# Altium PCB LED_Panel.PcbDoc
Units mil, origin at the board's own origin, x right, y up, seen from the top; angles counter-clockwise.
Board outline 1969 x 1969 mil, 2 copper layers (Top Layer, Bottom Layer); 87 components, 51 nets, 309 pads, 50 vias.
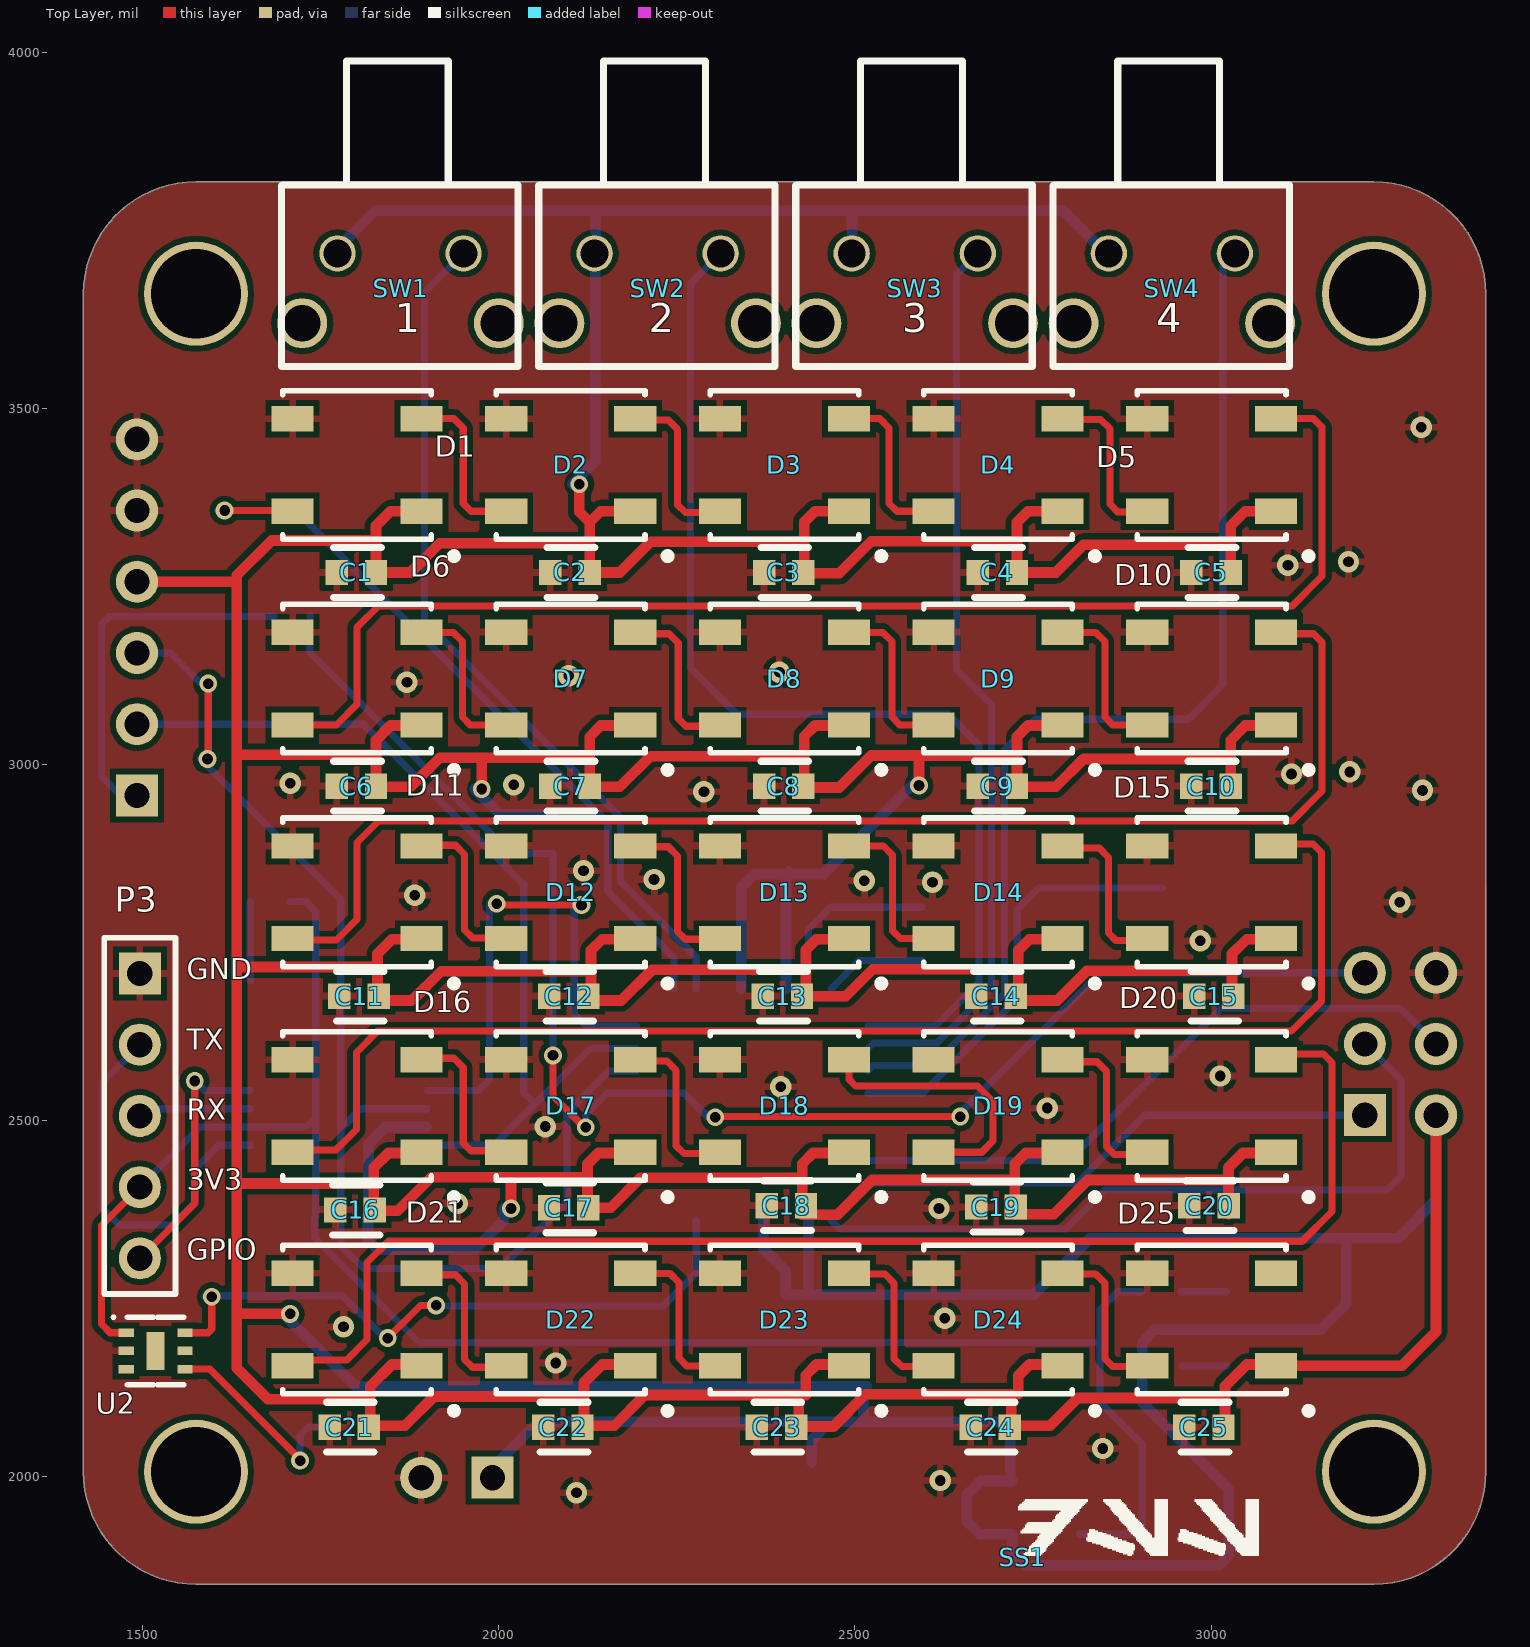
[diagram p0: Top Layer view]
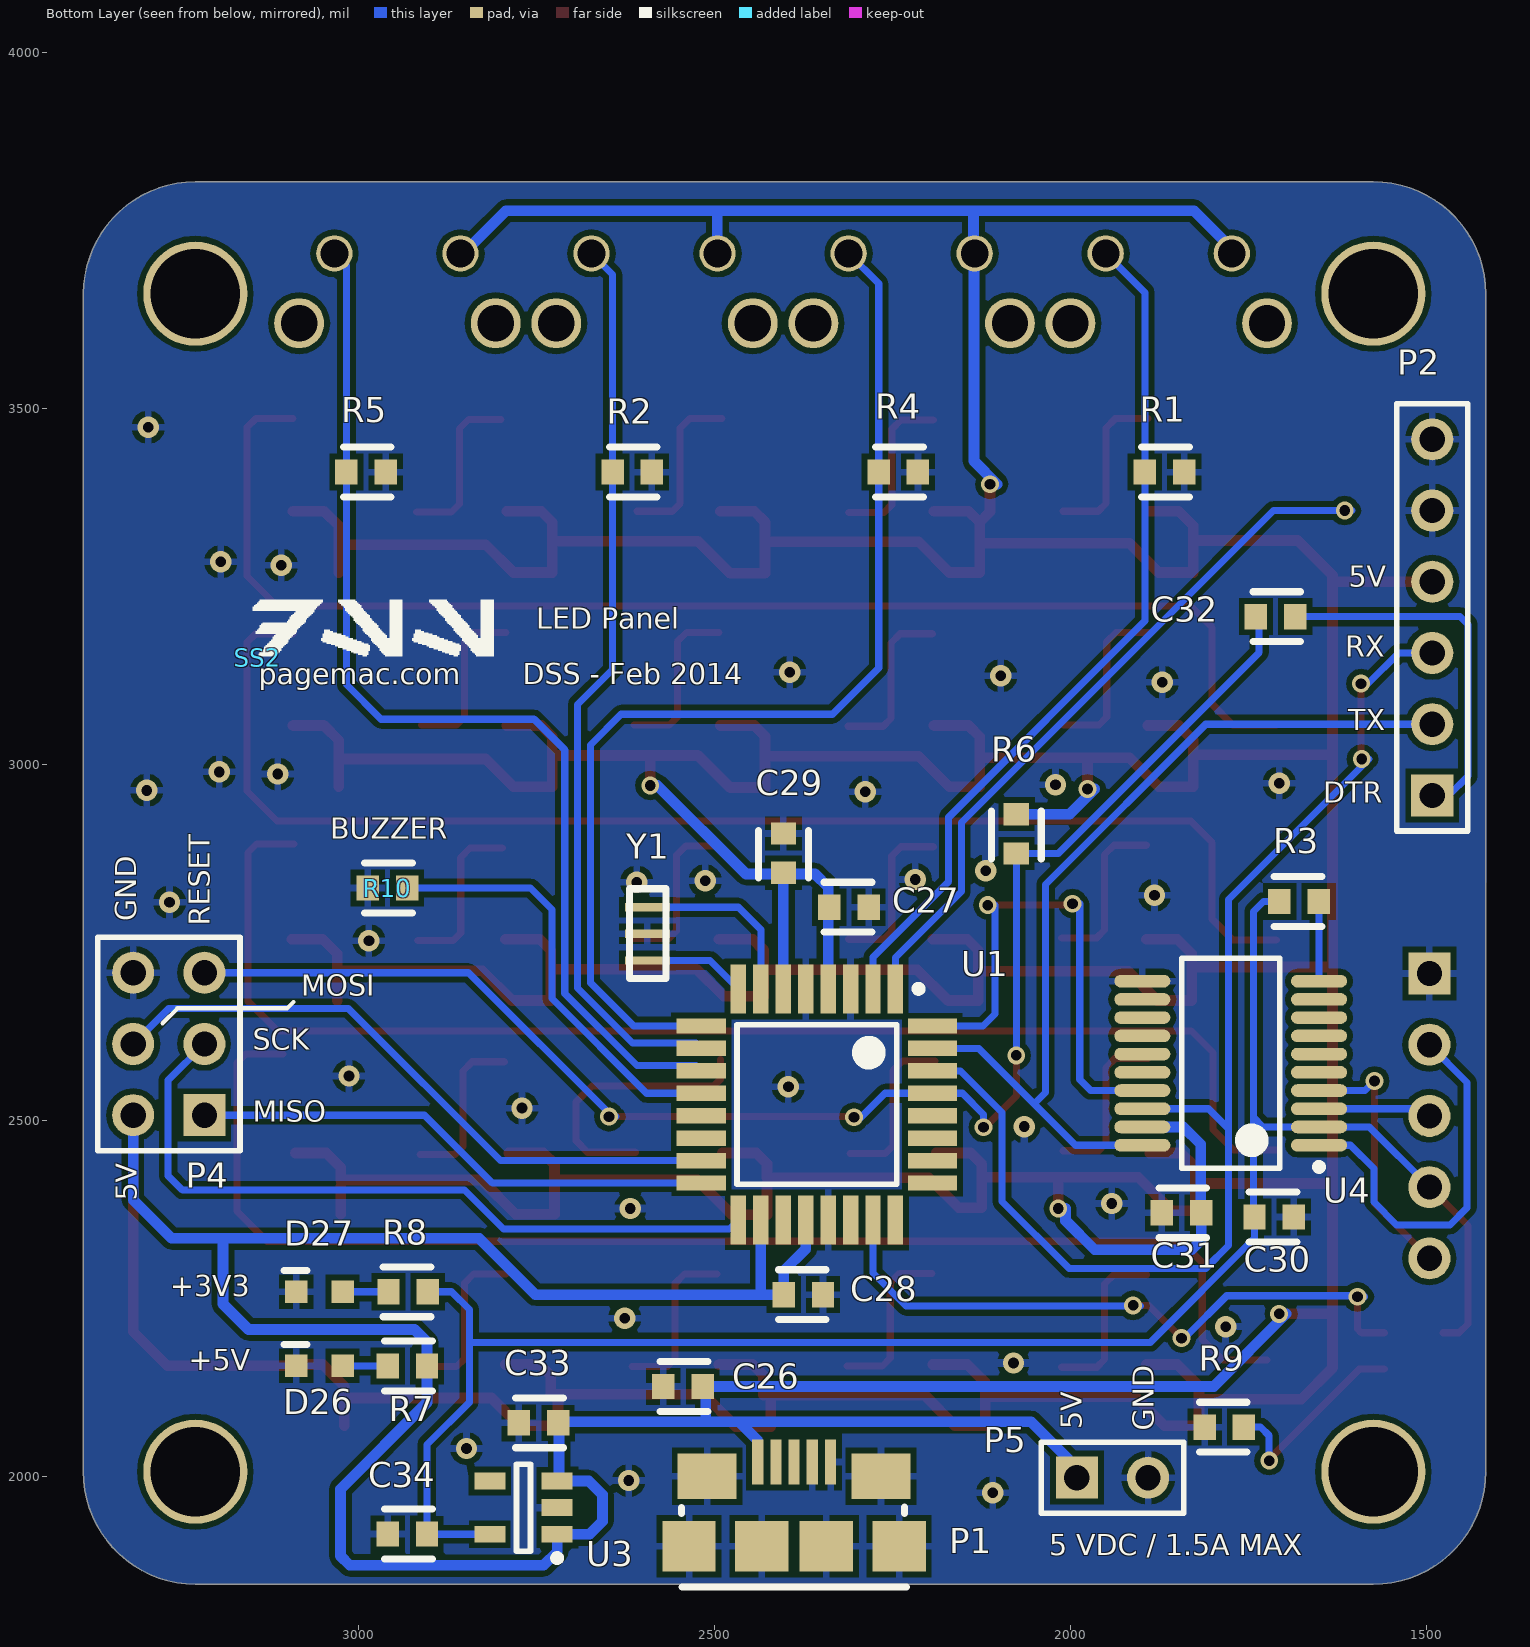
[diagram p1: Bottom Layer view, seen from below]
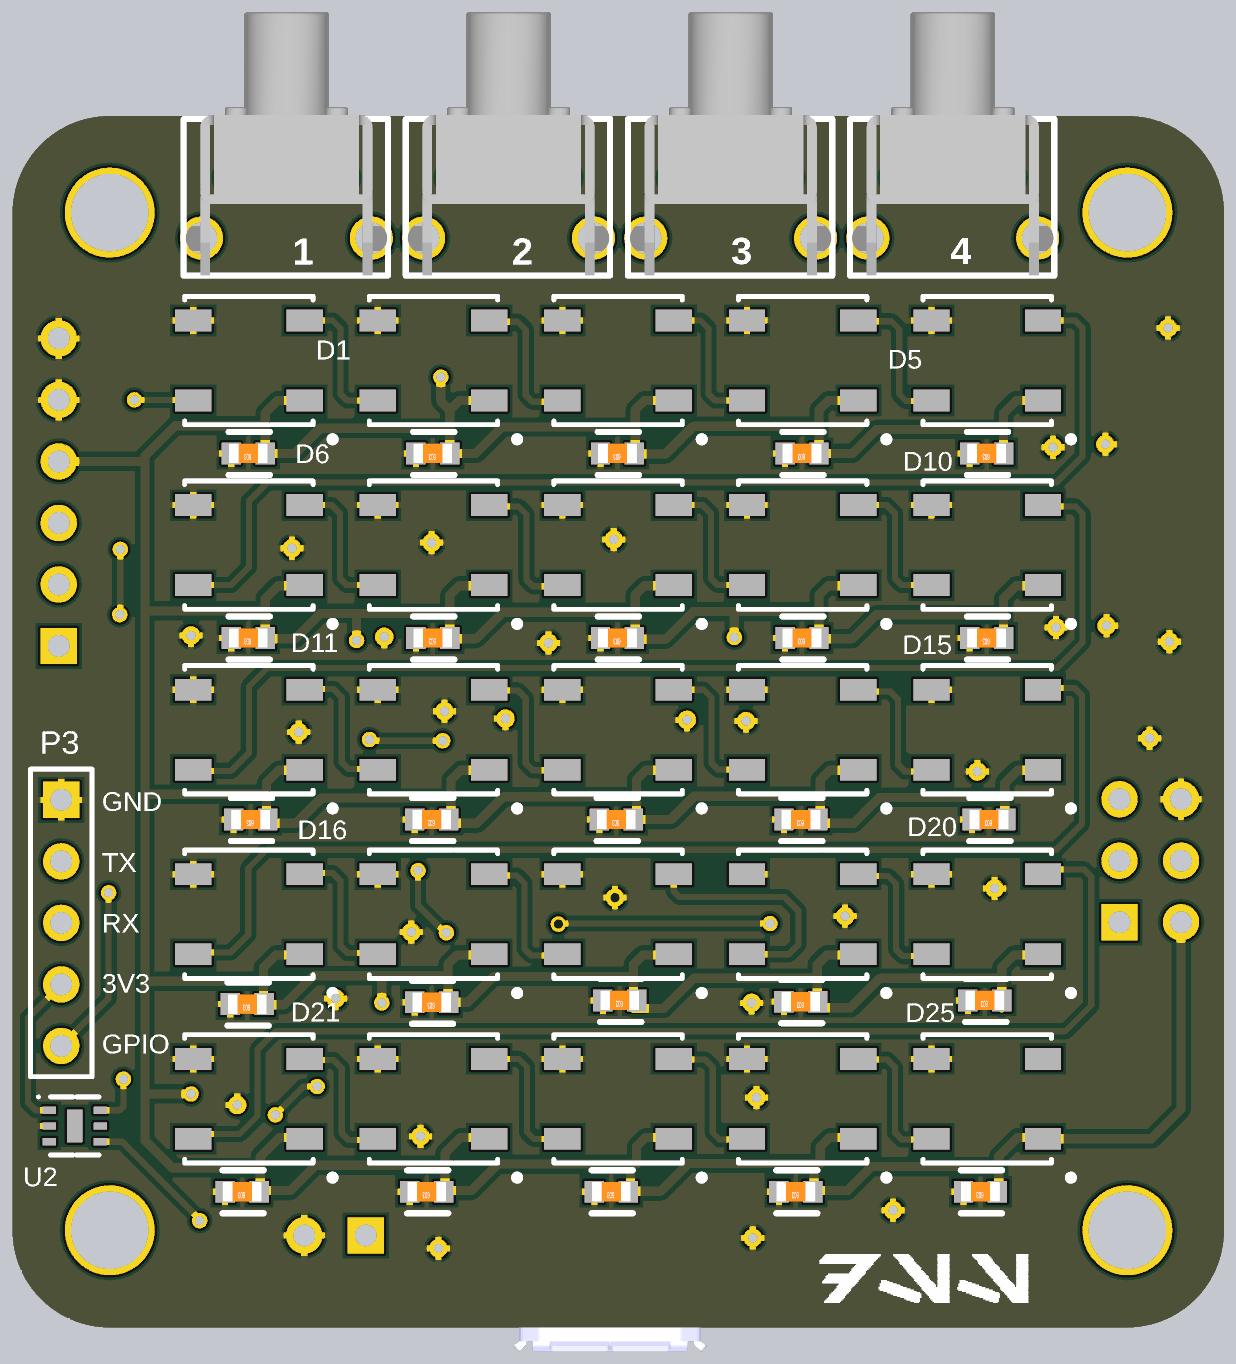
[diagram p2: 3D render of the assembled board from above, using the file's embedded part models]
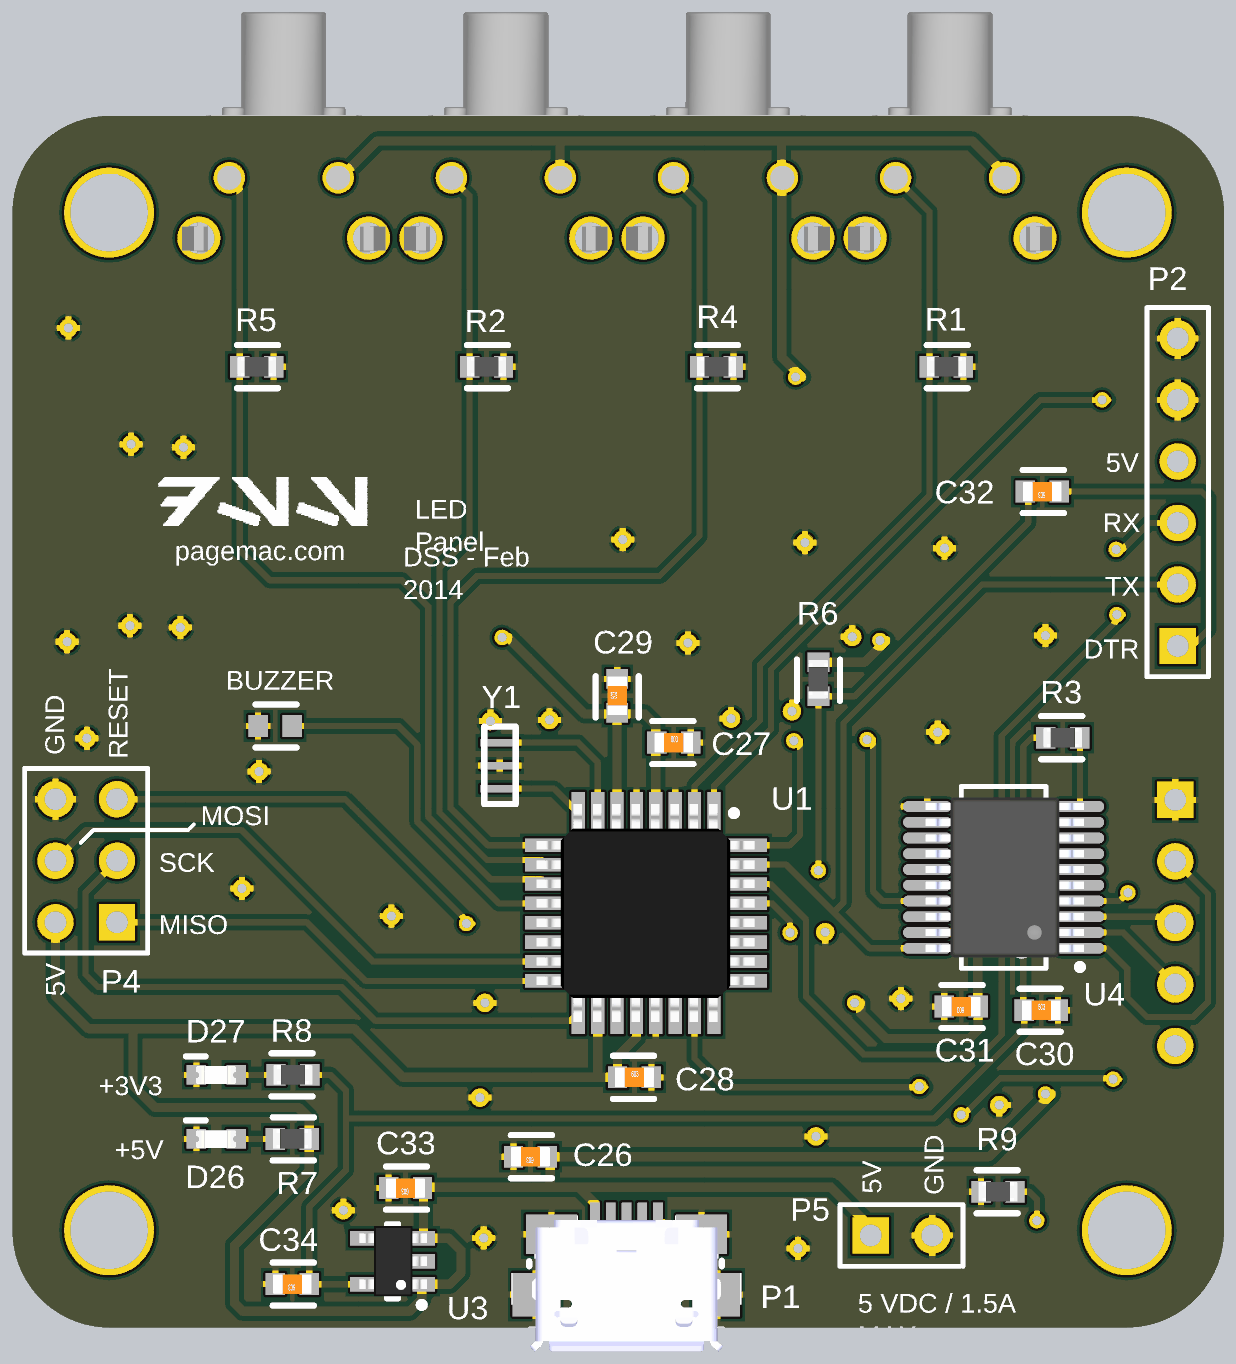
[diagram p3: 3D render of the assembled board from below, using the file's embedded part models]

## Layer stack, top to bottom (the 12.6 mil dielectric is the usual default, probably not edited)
Top Solder: solder mask 0.4, Solder Resist, Dk 3.5
Top Layer: signal copper 1.4
Dielectric 1: dielectric 12.6, FR-4, Dk 4.8
Bottom Layer: signal copper 1.4
Bottom Solder: solder mask 0.4, Solder Resist, Dk 3.5

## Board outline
1416.8,2007.42 1416.8,3661.42 cw(c1574.3,3660.92) 1574.8,3818.42 3228.8,3818.42 cw(c3228.8,3661.42) 3385.8,3661.42 3385.8,2007.42 cw(c3228.3,2006.92) 3228.8,1849.42 1574.8,1849.42 cw(c1574.8,2007.42)

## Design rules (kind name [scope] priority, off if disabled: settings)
Clearance ClearancePads [IsPad vs IsPad] p1: gap=6
Clearance [All] p2: gap=8
HoleSize [All] p1: absolutevalues=TRUE maxlimit=1000 minlimit=15 maxpercent=80.000 minpercent=20.000
PolygonConnect [All] p1: connectstyle=Relief reliefconductorwidth=10 reliefentries=4 polygonreliefangle="90 Angle" airgapwidth=8
RoutingVias [All] p1: holewidth=15 width=25 viastyle="Through Hole" minholewidth=15 minwidth=25 maxholewidth=15 maxwidth=25
SolderMaskExpansion [All] p1: expansion=4
Width WidthPower [InNetClass('Power')] p1: maxlimit=20 minlimit=10 preferedwidth=15 minimp=50.000000 maximp=50.000000 favimp=50.000000
Width [All] p2: maxlimit=10 minlimit=10 preferedwidth=10
28 further rules are at their usual default settings.

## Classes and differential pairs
net class Power: +5V

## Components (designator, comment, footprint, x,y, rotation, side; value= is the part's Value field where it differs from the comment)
C1 "CC0603KRX7R9BB104" C0603 1800,3270 r180 top
C2 "CC0603KRX7R9BB104" C0603 2100,3270 r180 top
C3 "CC0603KRX7R9BB104" C0603 2400,3270 r180 top
C4 "CC0603KRX7R9BB104" C0603 2700,3270 r180 top
C5 "CC0603KRX7R9BB104" C0603 3000,3270 r180 top
C6 "CC0603KRX7R9BB104" C0603 1800,2970 r180 top
C7 "CC0603KRX7R9BB104" C0603 2100,2970 r180 top
C8 "CC0603KRX7R9BB104" C0603 2400,2970 r180 top
C9 "CC0603KRX7R9BB104" C0603 2700,2970 r180 top
C10 "CC0603KRX7R9BB104" C0603 3000,2970 r180 top
C11 "CC0603KRX7R9BB104" C0603 1803.81,2675 r180 top
C12 "CC0603KRX7R9BB104" C0603 2098.19,2675 r180 top
C13 "CC0603KRX7R9BB104" C0603 2398.19,2675 r180 top
C14 "CC0603KRX7R9BB104" C0603 2698.19,2675 r180 top
C15 "CC0603KRX7R9BB104" C0603 3003.81,2675 r180 top
C16 "CC0603KRX7R9BB104" C0603 1798.19,2375 r180 top
C17 "CC0603KRX7R9BB104" C0603 2098,2378 r180 top
C18 "CC0603KRX7R9BB104" C0603 2403.81,2381 r180 top
C19 "CC0603KRX7R9BB104" C0603 2698,2379 r180 top
C20 "CC0603KRX7R9BB104" C0603 2997.19,2381 r180 top
C21 "CC0603KRX7R9BB104" C0603 1790,2070 r180 top
C22 "CC0603KRX7R9BB104" C0603 2090,2070 r180 top
C23 "CC0603KRX7R9BB104" C0603 2390,2070 r180 top
C24 "CC0603KRX7R9BB104" C0603 2690,2070 r180 top
C25 "CC0603KRX7R9BB104" C0603 2990,2070 r180 top
C26 "C1608X5R1A106M080AC" C0603 2544,2127 r0 bottom
C27 "CC0603KRX7R9BB104" C0603 2311,2800 r180 bottom
C28 "CC0603KRX7R9BB104" C0603 2375,2256 r180 bottom
C29 "CC0603KRX7R9BB104" C0603 2403,2876 r90 bottom
C30 "CC0603KRX7R9BB104" C0603 1714,2365 r180 bottom
C31 "CC0603KRX7R9BB104" C0603 1844,2371 r0 bottom
C32 "CC0603KRX7R9BB104" C0603 1712,3208 r0 bottom
C33 "CC0603KRX7R9BB104" C0603 2747,2076 r0 bottom
C34 "CC0603KRX7R9BB104" C0603 2931,1920 r0 bottom
D1 "WS2812B" WS2812B 1800,3420 r180 top
D2 "WS2812B" WS2812B 2100,3420 r180 top
D3 "WS2812B" WS2812B 2400,3420 r180 top
D4 "WS2812B" WS2812B 2700,3420 r180 top
D5 "WS2812B" WS2812B 3000,3420 r180 top
D6 "WS2812B" WS2812B 1800,3120 r180 top
D7 "WS2812B" WS2812B 2100,3120 r180 top
D8 "WS2812B" WS2812B 2400,3120 r180 top
D9 "WS2812B" WS2812B 2700,3120 r180 top
D10 "WS2812B" WS2812B 3000,3120 r180 top
D11 "WS2812B" WS2812B 1800,2820 r180 top
D12 "WS2812B" WS2812B 2100,2820 r180 top
D13 "WS2812B" WS2812B 2400,2820 r180 top
D14 "WS2812B" WS2812B 2700,2820 r180 top
D15 "WS2812B" WS2812B 3000,2820 r180 top
D16 "WS2812B" WS2812B 1800,2520 r180 top
D17 "WS2812B" WS2812B 2100,2520 r180 top
D18 "WS2812B" WS2812B 2400,2520 r180 top
D19 "WS2812B" WS2812B 2700,2520 r180 top
D20 "WS2812B" WS2812B 3000,2520 r180 top
D21 "WS2812B" WS2812B 1800,2220 r180 top
D22 "WS2812B" WS2812B 2100,2220 r180 top
D23 "WS2812B" WS2812B 2400,2220 r180 top
D24 "WS2812B" WS2812B 2700,2220 r180 top
D25 "WS2812B" WS2812B 3000,2220 r180 top
D26 "LTST-C190KGKT" LED_0603 2987,2191 r0 bottom
D27 "LTST-C190KGKT" LED_0603 2987,2295.06 r0 bottom
P1 "Micro USB" FCI/10118192-0001LF 2594,1791 r180 bottom
P2 "Arduino Programming" HDR1X6 1492,2957 r90 bottom
P3 "Serial Control" HDR1X5 1496,2707 r270 top
P4 "AVR Programming" HDR2X3 3216,2508 r90 bottom
P5 "Alt Power" HDR1X2 1991,1999 r180 bottom
R1 "ERJ-3EKF1002V" R0603 1868,3411 r0 bottom
R2 "ERJ-3EKF1002V" R0603 2615.33,3411 r0 bottom
R3 "ERJ-3EKF1002V" R0603 1679,2808 r180 bottom
R4 "ERJ-3EKF1002V" R0603 2241.67,3411 r0 bottom
R5 "ERJ-3EKF1002V" R0603 2989,3411 r0 bottom
R6 "ERJ-3EKF1002V" R0603 2076,2903 r90 bottom
R7 "ERJ-3GEYJ331V" R0603 2931,2156 r0 bottom
R8 "RC0603FR-07232KL" R0603 2930,2260.06 r180 bottom
R9 "ERJ-3EKF1003V" R0603 1784,2070 r180 bottom
R10 "Empty 0603" R0603_BLANK 2959,2827 r0 bottom
SS1 "DSS" DSS_LOGO 2736,1887 r0 top
SS2 "DSS" DSS_LOGO 3141,3150 r180 bottom
SW1 "FSMRA6JH" SWITCH_RA 2000,3620 r180 top
SW2 "FSMRA6JH" SWITCH_RA 2361,3620 r180 top
SW3 "FSMRA6JH" SWITCH_RA 2722,3620 r180 top
SW4 "FSMRA6JH" SWITCH_RA 3083,3620 r180 top
U1 "ATmega328P-AU" TQFP-32 2356,2523 r270 bottom
U2 "ISL76671AROZ-T7A" ODFN-6 1518,2177 r0 top
U3 "TLV70233DBVR" SOT23-5 2768,1957 r0 bottom
U4 "TXB0108PWR" TSSOP-20 1775,2581 r0 bottom
Y1 "CSTCE16M0V53-R0" MURATA_CRYSTAL 2594,2800 r270 bottom

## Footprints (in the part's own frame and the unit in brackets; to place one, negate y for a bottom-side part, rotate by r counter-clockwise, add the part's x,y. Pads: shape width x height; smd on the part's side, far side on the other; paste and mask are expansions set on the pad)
C0603 [mm] "Chip Capacitor, Body 1.6x0.8mmx0.9mm"
  rect 0.8x0.9 smd: 1(-0.7,0) 2(0.7,0)
  silkscreen extent -0.89,-0.89 0.81,0.89, body extent -0.8,-0.4 0.8,0.4, height 0.3
DSS_LOGO [mil]
  silkscreen extent -7,3 331,81
FCI/10118192-0001LF [mm] "USB Micro B, all surface mount, no holes"
  rect 0.4x1.604 smd: 1(3.932,5.842) 2(4.582,5.842) 3(5.232,5.842) 4(5.882,5.842) 5(6.532,5.842)
  rect 1.9x1.8 smd: 6(1.486,2.84) 6(4.082,2.84) 6(6.382,2.84) 6(8.978,2.84)
  rect 2.103x1.622 smd: 6(2.134,5.334) 6(8.331,5.334)
  silkscreen extent 1.22,1.39 9.23,4.24, body extent 0.48,0.49 9.98,6.43, height 2.74
HDR1X2 [mm] "Connector; Header; 2 Position"
  rect 1.5x1.5 hole 0.9: 1(0,0)
  round 1.5 hole 0.9: 2(2.54,0)
  silkscreen extent -1.27,-1.27 3.81,1.27
HDR1X5 [mm] "Connector; Header; 5 Position"
  rect 1.5x1.5 hole 0.9: 1(0,0)
  round 1.5 hole 0.9: 2(2.54,0) 3(5.08,0) 4(7.62,0) 5(10.16,0)
  silkscreen extent -1.27,-1.27 11.43,1.27
HDR1X6 [mm] "Connector; Header; 6 Position"
  rect 1.5x1.5 hole 0.9: 1(0,0)
  round 1.5 hole 0.9: 2(2.54,0) 3(5.08,0) 4(7.62,0) 5(10.16,0) 6(12.7,0)
  silkscreen extent -1.27,-1.27 13.97,1.27
HDR2X3 [mm] "Connector; Header; 3x2 Position"
  rect 1.5x1.5 hole 0.9: 1(0,0)
  round 1.5 hole 0.9: 2(0,2.54) 3(2.54,0) 4(2.54,2.54) 5(5.08,0) 6(5.08,2.54)
  silkscreen extent -1.27,-1.27 6.35,3.81
LED_0603 [mm]
  rect 0.8x0.8 smd: 1(0.889,0.889) 2(2.539,0.889)
  silkscreen extent 2.16,0.13 2.97,0.13, body extent 0.9,0.53 2.55,1.26, height 0.68
MURATA_CRYSTAL [mm] "3 pads, 3.2x1.3mm"
  rect 0.3x1.6 smd: 1(0,0) 2(0.95,0) 3(1.9,0)
  silkscreen extent -0.66,-0.64 2.54,0.66
ODFN-6 [mm]
  rect 0.55x0.3 smd: 1(-1.05,0.65) 2(-1.05,0) 3(-1.05,-0.65) 4(1.05,-0.65) 5(1.05,0) 6(1.05,0.65)
  rect 0.65x1.35 smd: 7(0,0)
  silkscreen extent -1.55,-1.2 1,1.25, body extent -1,-1.05 1,1.05, height 0.75
R0603 [mm] "Chip Resistor, Body 1.6x0.8mmx0.9mm"
  rect 0.8x0.9 smd: 1(-0.7,0) 2(0.7,0)
  silkscreen extent -0.89,-0.89 0.81,0.89, body extent -0.8,-0.4 0.8,0.4, height 0.37
R0603_BLANK [mm] "Chip Resistor, Body 1.6x0.8mmx0.9mm"
  rect 0.8x0.9 smd: 1(-0.7,0) 2(0.7,0)
  silkscreen extent -0.89,-0.89 0.81,0.89
SOT23-5 [mm] "SOT23, 5-Leads, Body 2.90x2.80mm, Pitch 0.95mm, IPC Medium Density"
  rect 1.1x0.6 smd: 1(-1.2,0.95) 2(-1.2,0) 3(-1.2,-0.95) 4(1.2,-0.95) 5(1.2,0.95)
  silkscreen extent -1.32,-1.55 0.25,1.92, body extent -1.43,-1.45 1.37,1.45, height 1.45
SWITCH_RA [mil] "CKN9120-ND"
  round 70 hole 51: 0(0,0) 0(276,0)
  round 51 hole 39: 1(49.5,-98) 2(226.5,-98)
  silkscreen extent -27,-368 305,61, body extent -27,-367 304,61, height 276
TQFP-32 [mm] "TQFP, 32-Leads, Body 7.00x7.00mm, Pitch 0.80mm, IPC Medium Density"
  rect 1.75x0.55 smd: 1(-4.125,2.8) 2(-4.125,2) 3(-4.125,1.2) 4(-4.125,0.4) 5(-4.125,-0.4) 6(-4.125,-1.2) 7(-4.125,-2) 8(-4.125,-2.8) 17(4.125,-2.8) 18(4.125,-2) 19(4.125,-1.2) 20(4.125,-0.4) 21(4.125,0.4) 22(4.125,1.2) 23(4.125,2) 24(4.125,2.8)
  rect 0.55x1.75 smd: 9(-2.8,-4.125) 10(-2,-4.125) 11(-1.2,-4.125) 12(-0.4,-4.125) 13(0.4,-4.125) 14(1.2,-4.125) 15(2,-4.125) 16(2.8,-4.125) 25(2.8,4.125) 26(2,4.125) 27(1.2,4.125) 28(0.4,4.125) 29(-0.4,4.125) 30(-1.2,4.125) 31(-2,4.125) 32(-2.8,4.125)
  silkscreen extent -4.25,-2.85 2.85,3.75, body extent -4.5,-4.53 4.5,4.47, height 1.47
TSSOP-20 [mm] "SOP, 20-Leads, Body 7.20x5.30mm, Pitch 0.65mm, IPC Medium Density"
  oval 2x0.45 smd: 1(-3.15,2.925) 2(-3.15,2.275) 3(-3.15,1.625) 4(-3.15,0.975) 5(-3.15,0.325) 6(-3.15,-0.325) 7(-3.15,-0.975) 8(-3.15,-1.625) 9(-3.15,-2.275) 10(-3.15,-2.925) 11(3.15,-2.925) 12(3.15,-2.275) 13(3.15,-1.625) 14(3.15,-0.975) 15(3.15,-0.325) 16(3.15,0.325) 17(3.15,0.975) 18(3.15,1.625) 19(3.15,2.275) 20(3.15,2.925)
  silkscreen extent -3.27,-3.75 1.75,3.82, body extent -3.33,-3.3 3.22,3.3, height 1.2
WS2812B [mm]
  rect 1.5x0.9 smd: 1(-2.325,1.625) 2(-2.325,-1.675) 3(2.275,-1.675) 4(2.275,1.625)
  silkscreen extent -3.6,-2.68 2.62,3.35, body extent -2.53,-2.53 2.47,2.47, height 1.63

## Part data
C1 C2 C3 C4 C5 C6 C7 C8 C9 C10 C11 C12 C13 C14 C15 C16 C17 C18 C19 C20 C21 C22 C23 C24 C25 C27 C28 C29 C30 C31 C32 C33 C34: "CAP CER 0.1UF 50V 10% X7R 0603"
C26: "CAP CER 10UF 10V 20% X5R 0603"
D1 D2 D3 D4 D5 D6 D7 D8 D9 D10 D11 D12 D13 D14 D15 D16 D17 D18 D19 D20 D21 D22 D23 D24 D25: "RGB LED WITH CONTROLLER"
D26 D27: "LED GREEN CLEAR 0603 SMD"
P1: library part 10118192-0001LF, "CONN USB MICRO B RECPT SMT R/A"
P2: library part "Header 6", "Header, 6-Pin"
P3: library part "Header 5", "Header, 5-Pin"
P4: library part "Header 3X2", "Header, 3-Pin, Dual row"
P5: library part "Header 2", "Header, 2-Pin"
R1 R2 R3 R4 R5 R6: "RES 10.0K OHM 1/10W 1% 0603 SMD"
R7: "RES 330 OHM 1/10W 5% 0603 SMD"
R8: "RES 232K OHM 1/10W 1% 0603 SMD"
R9: "RES 100K OHM 1/10W 1% 0603 SMD"
R10: library part Blank-Res-0603, "Empty 0603 Pads w/ Blank Resistor Puppet"
SW1 SW2 SW3 SW4: "SWITCH TACTILE SPST-NO 0.05A 12V"
U1: "8-bit AVR Microcontroller, 32KB Flash, 1KB EEPROM, 2KB SRAM, 32-pin TQFP, Industrial Grade (-40°C to 85°C)"
U2: "IC AMBIENT LIGHT SENSOR"
U3: "Single Output LDO, 300 mA, Fixed 3.3 V Output, 2 to 5.5 V Input, with Low IQ, 5-pin SOT-23 (DBV), -40 to 125 degC, Green (RoHS & no Sb/Br)"
U4: "IC VOLT-LVL TRANSL 8BIT 20-TSSOP"
Y1: "CER RESONATOR 16.0MHZ SMD"

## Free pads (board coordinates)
  round 146 hole 126: 1(1574.8,2007.42) 1(1574.8,3661.42) 1(3228.8,2007.42) 1(3228.8,3661.42)

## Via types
v1: diameter 30, hole 15, Top Layer to Bottom Layer, 31 vias
v2: diameter 25, hole 15, Top Layer to Bottom Layer, 19 vias

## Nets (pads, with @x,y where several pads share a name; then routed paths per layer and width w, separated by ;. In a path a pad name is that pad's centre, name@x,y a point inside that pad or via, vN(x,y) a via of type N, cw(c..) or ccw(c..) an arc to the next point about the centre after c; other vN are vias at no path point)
+3V3: C30.1 C34.1 P3.4 R3.1 R8.2 U2.1 U3.5 U4.2 | length 2702.5
  Top Layer w10: U2.1 1454.41,2202.59 1442,2215 1442,2353 P3.4
  Bottom Layer w10: P3.4 1580.43,2491.43 U4.2 1729.43,2491.43 1743,2505 ; R3.1 1729,2808 1743,2794 1743,2505 ; U3.5 C34.1@2903.04,1919.6 ; R8.2 2869.06,2260.06 2844,2235 2844,2189 ; C34.1 2903.44,2045.56 2844,2105 2844,2189 ; 1743,2505 1743,2366.44 C30.1 1741.56,2335.44 1888,2189 2844,2189
+5V: C1.1 C2.1 C3.1 C4.1 C5.1 C6.1 C7.1 C8.1 C9.1 C10.1 C11.1 C12.1 C13.1 C14.1 C15.1 C16.1 C17.1 C18.1 C19.1 C20.1 C21.1 C22.1 C23.1 C24.1 C25.1 C26.1 C27.1 C28.1 C29.1 C31.1 C33.1 D1.1 D2.1 D3.1 D4.1 D5.1 D6.1 D7.1 D8.1 D9.1 D10.1 D11.1 D12.1 D13.1 D14.1 D15.1 D16.1 D17.1 D18.1 D19.1 D20.1 D21.1 D22.1 D23.1 D24.1 D25.1 P1.1 P2.4 P4.2 P5.1 R6.2 R7.1 SW1.2 SW2.2 SW3.2 SW4.2 U1.4 U1.6 U1.18 U1.20 U3.1 U3.3 U4.19 | length 20089.1
  Top Layer w15: P2.4 1630,3257 ; 1633,2412 1824.56,2412 ; 1635,2229 v2(1707,2229) ; 1635,3014 1827.56,3014 ; 1636,2716 1829.56,2716 ; D16.1@1888.55,2455.04 1845.04,2455.04 1824.56,2434.56 1824.56,2412 ; D6.1@1891.55,3055.04 1848.04,3055.04 1827.56,3034.56 1827.56,3014 ; D1.1 1848.04,3356.04 1827.56,3335.56 1827.56,3315 ; D21.1@1893.55,2158.04 1850.04,2158.04 1819.56,2127.56 1819.56,2109 ; D11.1@1893.55,2755.04 1850.04,2755.04 1829.56,2734.56 1829.56,2716 ; v2(1976,2966) 1976,3010 ; v2(2017,2377) 2017,2418 ; v2(2113,3394) 2113,3355.12 2127.56,3340.56 ; D17.1@2188.55,2455.04 2140.04,2455.04 2124.56,2439.56 2124.56,2421 ; D7.1@2191.55,3055.04 2143.04,3055.04 2127.56,3039.56 2127.56,3010 ; D2.1 2143.04,3356.04 2127.56,3340.56 ; D22.1@2193.55,2158.04 2145.04,2158.04 2119.56,2132.56 2119.56,2113 ; D12.1@2193.55,2755.04 2145.04,2755.04 2129.56,2739.56 2129.56,2710 ; 2421,2115 2421,2071 2470,2071 2515,2116 2729.56,2116 2729.56,2142.56 2745.04,2158.04 D24.1@2793.55,2158.04 ; 2426,2412 2426,2368 2475,2368 2524,2417 2724.56,2417 2724.56,2439.56 2740.04,2455.04 D19.1@2788.55,2455.04 ; D18.1@2488.55,2455.04 2441.04,2455.04 2426,2440 2426,2420 2199,2420 2157,2378 2124.56,2378 2124.56,2421 ; D8.1@2491.55,3055.04 2444.04,3055.04 2429,3040 2429,3012 ; D3.1 2444.04,3356.04 2429,3341 2429,3313 ; D23.1@2493.55,2158.04 2446.04,2158.04 2431,2143 2431,2115 2205,2115 2162,2072 2119.56,2072 2119.56,2113 ; D13.1@2493.55,2755.04 2446.04,2755.04 2431,2740 2431,2712 ; v2(2590,2971) 2590,3012 ; 2719.56,2116 2719.56,2072 2774,2072 2813,2111 3019.56,2111 ; 2724.56,2413 2724.56,2369 2779,2369 2827,2417 3024.56,2417 3024.56,2434.56 3045.04,2455.04 D20.1@3088.55,2455.04 ; D9.1@2791.55,3055.04 2743.04,3055.04 2727.56,3039.56 2727.56,3013 ; D4.1 2743.04,3356.04 2727.56,3340.56 2727.56,3314 ; D14.1@2793.55,2755.04 2745.04,2755.04 2729.56,2739.56 2729.56,2713 ; C25.1@3019.56,2072 3019.56,2111 ; C20.1@3024.56,2369 3024.56,2408 ; C10.1@3027.56,2969 3027.56,3008 ; C5.1 3027.56,3309 ; C15.1@3029.56,2669 3029.56,2734.56 3050.04,2755.04 D15.1@3093.55,2755.04 ; 3029.56,2711 2826,2711 2784,2669 2729.56,2669 2729.56,2713 ; D25.1@3081.55,2156.04 3268.04,2156.04 3316,2204 P4.2 ; D10.1@3091.55,3055.04 3048.04,3055.04 3027.56,3034.56 3027.56,3008 ; D5.1 3048.04,3356.04 3027.56,3335.56 3027.56,3309 ; D25.1@3093.55,2158.04 3050.04,2158.04 3019.56,2127.56 3019.56,2111 ; 1819.56,2109 1676,2109 1632,2153 1632,3266 1681,3315 1827.56,3315 ; 1819.56,2109 1819.56,2072 1868,2072 1909,2113 2119.56,2113 ; 1824.56,2412 1824.56,2376.19 C16.1 1826.75,2374 1858,2374 1905,2421 2124.56,2421 ; 1827.56,3014 C6.1 1827.56,2969 1876,2969 1917,3010 1976,3010 ; 1827.56,3315 C1.1 1876,3270 1917,3311 2127.56,3311 ; 1829.56,2716 1829.56,2669 1878,2669 1919,2710 2129.56,2710 ; 1976,3010 2127.56,3010 ; 2127.56,3010 2127.56,2969 2170,2969 2213,3012 2429,3012 ; 2127.56,3311 2127.56,3340.56 ; 2127.56,3311 C2.1 2170,3270 2213,3313 2429,3313 ; 2129.56,2710 2129.56,2669 2172,2669 2215,2712 2431,2712 ; 2429,3012 2429,2968 2478,2968 2523,3013 2727.56,3013 ; 2429,3313 2429,3269 2478,3269 2523,3314 2727.56,3314 ; 2431,2712 2431,2675 2487,2675 2525,2713 2729.56,2713 ; 2727.56,3013 2727.56,2969 2782,2969 2821,3008 3027.56,3008 ; 2727.56,3314 C4.1 2782,3270 2821,3309 3027.56,3309
  Bottom Layer w15: v2@1697,2229 1799,2127 C26.1 2512,2122.56 2512,2077.44 ; SW1.2@1768.5,3720 1826.5,3778 2792.5,3778 SW4.2@2850.5,3720 ; C31.1 1816.44,2332.56 1830,2319 1966,2319 2007,2360 v2@2007,2377 ; C31.1@1817,2364 1817,2467 1841.43,2491.43 U4.19 ; v2@1966,2966 2001.44,2930.56 R6.2 ; P5.1@2004,2026 2055.44,2077.44 2465.44,2077.44 ; v2@2103,3394 2135.5,3426.5 2135.5,3717 SW2.2 ; SW2.2@2136.17,3722 2136.17,3775.83 ; U1.4 2340.25,2828.25 2358.68,2846.68 C29.1@2403.24,2846.68 ; U1.20 2371.75,2320.25 2402.56,2289.44 C28.1 ; U1.6 C29.1@2403.24,2846.68 ; C29.1@2404,2847.44 C29.1@2407,2850.44 ; U1.18 2434.74,2258.74 2432,2256 C28.1 ; P1.1 2439.18,2051.18 2465.44,2077.44 ; SW3.2@2495.83,3721 2495.83,3776.17 ; v2@2580,2971 2455.68,2846.68 C29.1@2403.24,2846.68 ; P4.2 3316,2389 3262,2335 3190,2335 ; C28.1 2751,2256 2830,2335 3190,2335 ; 2465.44,2077.44 2512,2077.44 ; 2512,2077.44 2718,2077.44 2718,1997.16 U3.3 2676.4,1994.4 2657,1975 2657,1938 2675.4,1919.6 U3.1 2720.76,1895.24 2740,1876 3012,1876 3025,1889 3025,1983 2903.44,2104.56 R7.1 2903.44,2189.44 2921,2207 3154,2207 3190,2243 3190,2335
BUTTON1: R1.2 SW1.1 U1.2 | length 1213.5
  Bottom Layer w10: SW1.1 1895.56,3663.06 R1.2 1895.56,3201.9 2171,2926.46 2171,2836 2277.26,2729.74 U1.2
BUTTON2: R4.2 SW2.1 U1.9 | length 1563.9
  Bottom Layer w10: SW2.1 2269.23,3675.73 R4.2 2269.23,3135.77 2334,3071 2631,3071 2674,3028 2674,2694 2613.24,2633.24 U1.9
BUTTON3: R2.2 SW3.1 U1.10 | length 1272.8
  Bottom Layer w10: U1.10 2526.07,2609.41 2614.87,2609.41 2692,2686.54 2692,3084.56 2642.89,3133.67 R2.2 2642.89,3688.39 SW3.1
BUTTON4: R5.2 SW4.1 U1.11 | length 1535.5
  Bottom Layer w10: U1.11 2526.07,2577.91 2608.82,2577.91 2710,2679.09 2710,3021 2753,3064 2968,3064 3016.56,3112.56 R5.2 3016.56,3701.06 SW4.1
BUZZER: R10.1 U1.12 | length 605.9
  Bottom Layer w10: U1.12 2595.12,2538.75 2728,2671.63 2728,2797 2758,2827 R10.1
DIN: D1.4 U1.1 | length 1095.9
  Top Layer w10: v2(1615,3357) D1.4@1709.49,3357
  Bottom Layer w10: v2@1605,3357 1715,3357 2153,2919 2153,2822 2245.76,2729.24 U1.1
DTR: C32.1 P2.1 | length 521.2
  Bottom Layer w10: P2.1 1469,2957 1442,2984 1442,3197 1453,3208 C32.1
GND: C1.2 C2.2 C3.2 C4.2 C5.2 C6.2 C7.2 C8.2 C9.2 C10.2 C11.2 C12.2 C13.2 C14.2 C15.2 C16.2 C17.2 C18.2 C19.2 C20.2 C21.2 C22.2 C23.2 C24.2 C25.2 C26.2 C27.2 C28.2 C29.2 C30.2 C31.2 C33.2 C34.2 D1.3 D2.3 D3.3 D4.3 D5.3 D6.3 D7.3 D8.3 D9.3 D10.3 D11.3 D12.3 D13.3 D14.3 D15.3 D16.3 D17.3 D18.3 D19.3 D20.3 D21.3 D22.3 D23.3 D24.3 D25.3 D26.2 D27.2 P1.4 P1.5 P1.6 P2.5 P2.6 P3.1 P4.6 P5.2 R1.1 R2.1 R4.1 R5.1 R9.1 R10.2 U1.3 U1.5 U1.21 U2.2 U3.2 U4.11 Y1.2
  other v1: 2109,1978 2620,1995 2848,2040 2080,2160 1782,2211 2626,2223 2618,2377 1942,2384 2065,2492 2770,2518 2396,2548 3013,2563 2985,2753 3265,2807 1882,2817 2609,2835 2513,2837 2218,2839 2119,2851 2288,2962 3297,2964 2021,2972 1707,2974 3113,2987 3195,2990 1871,3116 2098,3125 2394,3130 3108,3280 3193,3285 3295,3474
GPIO_EXT: U1.32 U4.17 | length 708.7
  Top Layer w10: v2(1997,2805) 1999,2803 v2(2116,2803)
  Bottom Layer w10: U4.17 1971.61,2542.61 1987,2558 v2@1987,2805 ; v2@2106,2803 2106,2650 2122.76,2633.24 U1.32
GPIO_EXT_3V3: P3.5 U4.4 | length 364.4
  Top Layer w10: P3.5 1573,2384 v2(1573,2556)
  Bottom Layer w10: v2(1573,2556) 1586.39,2542.61 U4.4
LIGHT: U1.23 U2.6 | length 914.7
  Top Layer w10: U2.6 1591.59,2202.59 1597,2208 v2(1597,2253) ; v2(1844,2195) 1890,2241 v2(1912,2241)
  Bottom Layer w10: v2@1587,2253 1588.5,2254.5 1780.5,2254.5 v2@1837,2198 ; v2@1902,2240 2231,2240 2277.26,2286.26 U1.23
MISO: P4.1 U1.16 | length 737
  Bottom Layer w10: U1.16 2811.76,2412.76 2907,2508 P4.1
MOSI: P4.4 U1.15 | length 906.8
  Bottom Layer w10: U1.15 2800.26,2444.26 3014,2658 3266,2658 P4.4
NetD1_2: D1.2 D2.4 | length 234.8
  Top Layer w10: D1.2 1937.04,3485.96 1950,3473 1950,3367 1960.96,3356.04 D2.4
NetD2_2: D2.2 D3.4 | length 234.8
  Top Layer w10: D2.2@2192.55,3483.96 2238.04,3483.96 2251,3471 2251,3365 2261.96,3354.04 D3.4@2311.45,3354.04
NetD3_2: D3.2 D4.4 | length 234.8
  Top Layer w10: D3.2@2489.55,3485.96 2535.04,3485.96 2548,3473 2548,3367 2558.96,3356.04 D4.4@2608.45,3356.04
NetD4_2: D4.2 D5.4 | length 234.8
  Top Layer w10: D4.2@2799.55,3484.96 2845.04,3484.96 2858,3472 2858,3366 2868.96,3355.04 D5.4@2918.45,3355.04
NetD5_2: D5.2 D6.4 | length 1873.8
  Top Layer w10: D6.4 1772.04,3056.04 1801,3085 1801,3193 1831,3223 3114,3223 3156,3265 3156,3474 3144.04,3485.96 D5.2
NetD6_2: D6.2 D7.4 | length 234.8
  Top Layer w10: D6.2@1890.55,3185.96 1936.04,3185.96 1949,3173 1949,3067 1959.96,3056.04 D7.4@2009.45,3056.04
NetD7_2: D7.2 D8.4 | length 234.8
  Top Layer w10: D7.2@2193.55,3183.96 2239.04,3183.96 2252,3171 2252,3065 2262.96,3054.04 D8.4@2312.45,3054.04
NetD8_2: D8.2 D9.4 | length 234.8
  Top Layer w10: D8.2@2493.55,3185.96 2539.04,3185.96 2552,3173 2552,3067 2562.96,3056.04 D9.4@2612.45,3056.04
NetD9_2: D9.2 D10.4 | length 234.8
  Top Layer w10: D9.2@2792.55,3185.96 2838.04,3185.96 2851,3173 2851,3067 2861.96,3056.04 D10.4@2911.45,3056.04
NetD10_2: D10.2 D11.4 | length 1873.8
  Top Layer w10: D11.4@1710.45,2754.04 1772.04,2754.04 1801,2783 1801,2891 1831,2921 3114,2921 3156,2963 3156,3172 3144.04,3183.96 D10.2@3091.55,3183.96
NetD11_2: D11.2 D12.4 | length 234.8
  Top Layer w10: D11.2@1893.55,2886.96 1939.04,2886.96 1952,2874 1952,2768 1962.96,2757.04 D12.4@2012.45,2757.04
NetD12_2: D12.2 D13.4 | length 234.8
  Top Layer w10: D12.2@2192.55,2884.96 2238.04,2884.96 2251,2872 2251,2766 2261.96,2755.04 D13.4@2311.45,2755.04
NetD13_2: D13.2 D14.4 | length 234.8
  Top Layer w10: D13.2@2494.55,2885.96 2540.04,2885.96 2553,2873 2553,2767 2563.96,2756.04 D14.4@2613.45,2756.04
NetD14_2: D14.2 D15.4 | length 234.8
  Top Layer w10: D14.2@2797.55,2882.96 2843.04,2882.96 2856,2870 2856,2764 2866.96,2753.04 D15.4@2916.45,2753.04
NetD15_2: D15.2 D16.4 | length 1873.8
  Top Layer w10: D16.4@1709.45,2459.04 1771.04,2459.04 1800,2488 1800,2596 1830,2626 3113,2626 3155,2668 3155,2877 3143.04,2888.96 D15.2@3090.55,2888.96
NetD16_2: D16.2 D17.4 | length 234.8
  Top Layer w10: D16.2@1891.55,2587.96 1937.04,2587.96 1950,2575 1950,2469 1960.96,2458.04 D17.4@2010.45,2458.04
NetD17_2: D17.2 D18.4 | length 234.8
  Top Layer w10: D17.2@2190.55,2583.96 2236.04,2583.96 2249,2571 2249,2465 2259.96,2454.04 D18.4@2309.45,2454.04
NetD18_2: D18.2 D19.4 | length 388.1
  Top Layer w10: D18.2 2491.55,2558.45 2501,2549 2672,2549 2694,2527 2694,2472 2678.04,2456.04 D19.4
NetD19_2: D19.2 D20.4 | length 234.8
  Top Layer w10: D19.2@2794.55,2582.96 2840.04,2582.96 2853,2570 2853,2464 2863.96,2453.04 D20.4@2913.45,2453.04
NetD20_2: D20.2 D21.4 | length 1873.8
  Top Layer w10: D21.4@1724.45,2164.04 1786.04,2164.04 1815,2193 1815,2301 1845,2331 3128,2331 3170,2373 3170,2582 3158.04,2593.96 D20.2@3105.55,2593.96
NetD21_2: D21.2 D22.4 | length 234.8
  Top Layer w10: D21.2@1893.55,2283.96 1939.04,2283.96 1952,2271 1952,2165 1962.96,2154.04 D22.4@2012.45,2154.04
NetD22_2: D22.2 D23.4 | length 234.8
  Top Layer w10: D22.2@2194.55,2285.96 2240.04,2285.96 2253,2273 2253,2167 2263.96,2156.04 D23.4@2313.45,2156.04
NetD23_2: D23.2 D24.4 | length 234.8
  Top Layer w10: D23.2@2496.55,2284.96 2542.04,2284.96 2555,2272 2555,2166 2565.96,2155.04 D24.4@2615.45,2155.04
NetD24_2: D24.2 D25.4 | length 234.8
  Top Layer w10: D24.2@2792.55,2284.96 2838.04,2284.96 2851,2272 2851,2166 2861.96,2155.04 D25.4@2911.45,2155.04
NetD26_1: D26.1 R7.2 | length 63.4
  Bottom Layer w10: R7.2 D26.1
NetD27_1: D27.1 R8.1 | length 64.4
  Bottom Layer w10: R8.1 D27.1
NetR3_2: R3.2 U4.10 | length 112
  Bottom Layer w10: U4.10 1650.98,2807.54 R3.2
NetR9_2: R9.2 U2.4 | length 291.4
  Top Layer w10: U2.4 1594.6,2151.41 1721,2025.01 v2(1721,2023)
  Bottom Layer w10: v2(1721,2023) 1721,2058 1733,2070 R9.2
NetU1_7: U1.7 Y1.1 | length 255.5
  Bottom Layer w10: U1.7 2434.74,2768.74 2466,2800 Y1.1
NetU1_8: U1.8 Y1.3 | length 144.2
  Bottom Layer w10: U1.8 2506.03,2725.2 Y1.3
RESET: C32.2 P4.5 R6.1 U1.29 | length 2141.8
  Top Layer w10: v2(2076,2592) 2076,2535 2120,2491 v2(2122,2491) ; v2(2304,2505) 2305,2506 v2(2648,2506)
  Bottom Layer w10: C32.2@1735,3210 1735,3157.46 2017.02,2875.44 R6.1 2076,2589 v2@2075,2588 ; v2(2122,2491) 2122,2509 2151.75,2538.75 U1.29 2260.25,2538.75 v2@2294,2505 ; v2@2638,2506 2643,2506 2845,2708 P4.5
RX: P2.3 U1.30 U4.18 | length 1726.9
  Top Layer w10: v2@1592,3009 v2(1592,3114)
  Bottom Layer w10: P2.3 1539,3157 v2@1582,3114 ; v2@1581,3008 1778,2811 1778,2489 ; U4.18 1806.02,2517.02 1778,2489 ; U1.30 2154.24,2570.24 2096,2512 2096,2387 2002,2293 1810,2293 1778,2325 1778,2489
  other v2: 1591,3008
RX_3V3: P3.3 U4.3 | length 162
  Bottom Layer w10: P3.3@1494,2505 P3.3 1506.02,2517.02 U4.3
SCK: P4.3 U1.17 | length 1043.2
  Bottom Layer w10: U1.17 2478.83,2348 2796,2348 2851,2403 3247,2403 3267,2423 3267,2557 P4.3
TX: P2.2 U1.31 U4.20 | length 1300.3
  Bottom Layer w10: P2.2 1810,3057 2035,2832 2035,2540 2050,2525 ; U4.20 1992.84,2465.84 2128.74,2601.74 U1.31
TX_3V3: P3.2 U4.1 | length 542.7
  Bottom Layer w10: P3.2 1443,2554 1443,2378 1467,2354 1542,2354 1574,2386 1574,2433 1606.84,2465.84 U4.1
pads on no net: D25.2 P1.2 P1.3 SW1.0 SW2.0 SW3.0 SW4.0 U1.13 U1.14 U1.19 U1.22 U1.24 U1.25 U1.26 U1.27 U1.28 U2.3 U2.5 U2.7 U3.4 U4.5 U4.6 U4.7 U4.8 U4.9 U4.12 U4.13 U4.14 U4.15 U4.16

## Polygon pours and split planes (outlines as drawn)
GND on Bottom Layer "Top Layer-No Net1" (solid, pour order 6): 1416.8,2007.42 1416.8,3661.42 cw(c1574.3,3660.92) 1574.8,3818.42 3228.8,3818.42 cw(c3228.8,3661.42) 3385.8,3661.42 3385.8,2007.42 cw(c3228.3,2006.92) 3228.8,1849.42 1574.8,1849.42 cw(c1574.8,2007.42)
GND on Top Layer "Top Layer-No Net" (solid, pour order 4): 1416.8,2007.42 1416.8,3661.42 cw(c1574.3,3660.92) 1574.8,3818.42 3228.8,3818.42 cw(c3228.8,3661.42) 3385.8,3661.42 3385.8,2007.42 cw(c3228.3,2006.92) 3228.8,1849.42 1574.8,1849.42 cw(c1574.8,2007.42)

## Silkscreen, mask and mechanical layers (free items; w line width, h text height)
Top Overlay:
  text "1" at 1854,3594 h70
  text "2" at 2210.33,3594 h70
  text "3" at 2566.67,3594 h70
  text "4" at 2923,3594 h70
  text "GND" at 1562,2689 h50
  text "TX" at 1562,2589.98 h50
  text "RX" at 1562,2491.48 h50
  text "3V3" at 1562,2393.5 h50
  text "GPIO" at 1562,2295 h50
Bottom Overlay:
  lines w6: 3091,2667 3100,2658 3254,2658 3275,2637
  text "5V" at 1609,3240 h50
  text "LED Panel" at 2750,3181 h50
  text "RX" at 1614,3142 h50
  text "DSS - Feb 2014" at 2769,3103 h50
  text "pagemac.com" at 3140,3103 h50
  text "TX" at 1610,3039 h50
  text "DTR" at 1645,2937 h50
  text "BUZZER" at 3039,2886 h50
  text "GND" at 3302,2780 h50 r270
  text "RESET" at 3199,2774 h50 r270
  text "MOSI" at 3080,2666 h50
  text "SCK" at 3148,2590 h50
  text "MISO" at 3148,2489 h50
  text "5V" at 3301,2388 h50 r270
  text "+3V3" at 3264,2244 h50
  text "+5V" at 3238,2140 h50
  text "5V" at 1974,2067 h50 r270
  text "GND" at 1873,2065 h50 r270
  text "5 VDC / 1.5A MAX" at 2030,1880 h50
Mechanical 3:
  region: 1692.8,3818.42 1693.13,3661.42 1693.17,3660.92 1691.71,3642.32 1687.35,3624.19 1680.21,3606.95 1670.47,3591.05 1658.36,3576.87 1644.17,3564.75 1628.27,3555.01 1611.04,3547.87 1592.9,3543.51 1574.8,3542.09 1574.8,3542.42 1416.8,3542.42 1416.35,3661.42 1418.26,3685.63 1424.05,3709.74 1433.53,3732.64 1446.49,3753.78 1462.59,3772.63 1481.44,3788.73 1502.58,3801.69 1525.48,3811.17 1549.59,3816.96 1574.3,3818.91 1574.8,3818.87 1574.8,3818.42
  region: 1416.8,2125.42 1574.8,2125.78 1593.32,2124.32 1611.38,2119.99 1628.54,2112.88 1644.38,2103.18 1658.5,2091.11 1670.56,2076.99 1680.27,2061.15 1687.37,2043.99 1691.71,2025.93 1693.17,2007.42 1692.8,2007.42 1692.8,1849.42 1574.8,1848.93 1550.01,1850.88 1525.83,1856.69 1502.85,1866.2 1481.65,1879.2 1462.73,1895.35 1446.58,1914.26 1433.59,1935.46 1424.07,1958.44 1418.27,1982.62 1416.31,2007.42 1416.8,2007.42
  region: 3109.8,1849.42 3109.48,2007.42 3110.9,2025.51 3115.25,2043.65 3122.39,2060.88 3132.14,2076.79 3144.25,2090.97 3158.43,2103.08 3174.34,2112.83 3191.57,2119.97 3209.71,2124.32 3228.3,2125.78 3228.8,2125.75 3228.8,2125.42 3385.8,2125.42 3386.25,2007.42 3386.29,2006.92 3384.35,1982.2 3378.56,1958.1 3369.07,1935.19 3356.12,1914.05 3340.02,1895.2 3321.17,1879.1 3300.03,1866.15 3277.12,1856.66 3253.02,1850.87 3228.8,1848.97 3228.8,1849.42
  region: 3385.8,3542.42 3228.8,3542.05 3210.13,3543.52 3191.92,3547.89 3174.61,3555.06 3158.64,3564.85 3144.4,3577.01 3132.23,3591.25 3122.45,3607.23 3115.28,3624.53 3110.9,3642.74 3109.44,3661.42 3109.8,3661.42 3109.8,3818.42 3228.8,3818.9 3253.44,3816.96 3277.47,3811.19 3300.3,3801.74 3321.37,3788.83 3340.16,3772.78 3356.21,3753.99 3369.12,3732.91 3378.58,3710.08 3384.35,3686.05 3386.29,3661.42 3385.8,3661.42
Mechanical 5:
  the board outline again, w0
